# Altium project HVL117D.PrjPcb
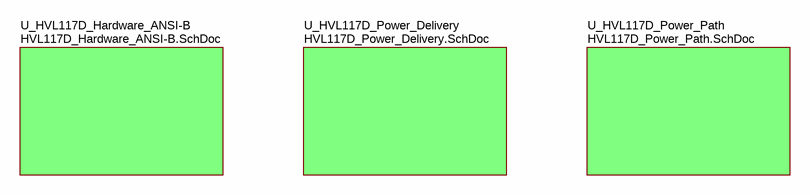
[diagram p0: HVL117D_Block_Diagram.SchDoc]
AssemblyVariant: =VariantName; CopyrightYear: 2015; PCB_Layout: Jacob Ontiveros; PCB_Rev: D; PRJ_Customer: Public Release; PRJ_Engineer: Jacob Ontiveros; PRJ_Number: HVL117; PRJ_Title: TPS65982EVM; SCH_Rev: D; TechSupport: j-ontiveros@ti.com
4 sheets, 220 parts. Net scope: global (net labels, ports and power ports of the same name join across sheets).
Board file: HVL117D.PcbDoc
Sheets:
  HVL117D_Block_Diagram.SchDoc
    U_HVL117D_Hardware_ANSI-B = HVL117D_Hardware_ANSI-B.SchDoc
    U_HVL117D_Power_Delivery = HVL117D_Power_Delivery.SchDoc
    U_HVL117D_Power_Path = HVL117D_Power_Path.SchDoc

## Sheet HVL117D_Block_Diagram.SchDoc: HVL117D_Block_Diagram
size 431 x 279 mm; Date: Not shown in title block; ApprovedBy: Not shown in title block; CheckedBy: Not shown in title block; Author: Not shown in title block; CompanyName: Not shown in title block; Engineer: Not shown in title block; Organization: Not shown in title block; Address1: Not shown in title block; Address2: Not shown in title block; Address3: Not shown in title block; Address4: Not shown in title block; DocumentNumber: 1; Revision: Use project parameter SCH_Rev; SheetNumber: 1; SheetTotal: 4; PageSetup: Record=PageOptions¦CenterHorizontal=True¦CenterVertical=True¦PrintScale=0.64¦XCorrection=1.00¦YCorrection=1.00¦PrintKind=0¦BorderSize=5000000¦LeftOffset=0¦BottomOffset=0¦Orientation=2¦PaperLength=1000¦PaperWidth=1000¦Scale=100¦PaperSource=15¦PrintQuality=600¦MediaType=1¦DitherType=10¦PaperKind=Letter¦PrintScaleMode=1

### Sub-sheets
U_HVL117D_Hardware_ANSI-B = HVL117D_Hardware_ANSI-B.SchDoc: no entries
U_HVL117D_Power_Delivery = HVL117D_Power_Delivery.SchDoc: no entries
U_HVL117D_Power_Path = HVL117D_Power_Path.SchDoc: no entries

## Sheet HVL117D_Hardware_ANSI-B.SchDoc: Hardware
size 431 x 279 mm; Date: Not shown in title block; ApprovedBy: Not shown in title block; CheckedBy: Not shown in title block; Author: Not shown in title block; CompanyName: Not shown in title block; Engineer: Not shown in title block; Organization: Not shown in title block; Address1: Not shown in title block; Address2: Not shown in title block; Address3: Not shown in title block; Address4: Not shown in title block; DocumentNumber: 4; Revision: Use project parameter SCH_Rev; SheetNumber: 4; SheetTotal: 4; PageSetup: Record=PageOptions¦CenterHorizontal=True¦CenterVertical=True¦PrintScale=1.00¦XCorrection=1.00¦YCorrection=1.00¦PrintKind=0¦BorderSize=5000000¦LeftOffset=0¦BottomOffset=0¦Orientation=2¦PaperLength=1000¦PaperWidth=1000¦Scale=100¦PaperSource=15¦PrintQuality=600¦MediaType=1¦DitherType=10¦PaperKind=Letter¦PrintScaleMode=1
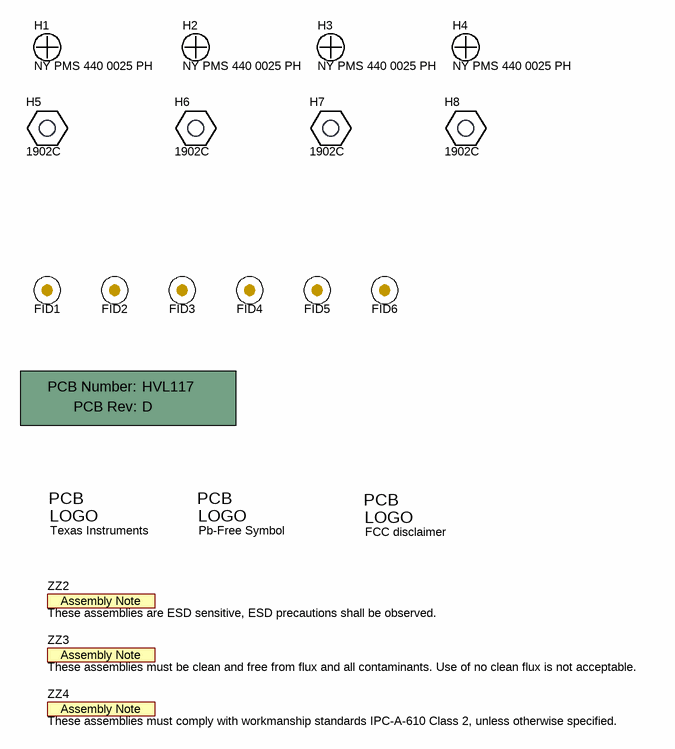
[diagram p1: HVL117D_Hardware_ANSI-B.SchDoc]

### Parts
!PCB1  Printed Circuit Board  (value not drawn)  (mechanical)
FID1  Fiducial  [Fiducial10-20]  (value not drawn)
FID2  Fiducial  [Fiducial10-20]  (value not drawn)
FID3  Fiducial  [Fiducial10-20]  (value not drawn)
FID4  Fiducial  [Fiducial10-20]  (value not drawn)
FID5  Fiducial  [Fiducial10-20]  (value not drawn)
FID6  Fiducial  [Fiducial10-20]  (value not drawn)
H1  NY PMS 440 0025 PH  [NY PMS 440 0025 PH]
H2  NY PMS 440 0025 PH  [NY PMS 440 0025 PH]
H3  NY PMS 440 0025 PH  [NY PMS 440 0025 PH]
H4  NY PMS 440 0025 PH  [NY PMS 440 0025 PH]
H5  1902C  [Keystone_1902C]
H6  1902C  [Keystone_1902C]
H7  1902C  [Keystone_1902C]
H8  1902C  [Keystone_1902C]
Logo1  Texas Instruments  [TI_Stacked_Overlay_Small]  (no BOM)
Logo2  Pb-Free Symbol  [Pb-Free_Overlay_Small]  (no BOM)
Logo3  FCC disclaimer  [FCC_disclaimer_stacked]  (no BOM)
ZZ2  These assemblies are ESD sensitive, ESD precautions shall be observed.  [AssemblyNote]  (no BOM)
ZZ3  These assemblies must be clean and free from flux and all contaminants. Use of no clean flux is not acceptable.  [AssemblyNote]  (no BOM)
ZZ4  These assemblies must comply with workmanship standards IPC-A-610 Class 2, unless otherwise specified.  [AssemblyNote]  (no BOM)

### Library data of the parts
!PCB1 = PCB: Manufacturer: Any; PartNumber: HVL117; SymbolCreator: a0412235
FID1-FID6 = Fiducial: Fiducial mark.  There is nothing to buy or mount.; SymbolCreator: codlsc
H1-H4 = NY PMS 440 0025 PH: Machine Screw, Round, #4-40 x 1/4, Nylon, Philips panhead; Manufacturer: B&F Fastener Supply; CompType: Hardware; SymbolCreator: codlsc; U/M: EA
H5-H8 = 1902C: Standoff, Hex, 0.5"L #4-40 Nylon; Manufacturer: Keystone; CompType: Hardware; SymbolCreator: a0412235
Logo1 = TI_Logo: Texas Instrument Corporate Signature; SymbolCreator: a0412235
Logo2 = Pb-Free: SymbolCreator: a0412235
Logo3 = FCC_disclaimer: SymbolCreator: codlsc
ZZ2-ZZ4 = AssemblyNote: SymbolCreator: codlsc

## Sheet HVL117D_Power_Delivery.SchDoc: TPS65982_TypeC_PD
size 431 x 279 mm; Date: Not shown in title block; ApprovedBy: Not shown in title block; CheckedBy: Not shown in title block; Author: Not shown in title block; CompanyName: Not shown in title block; Engineer: Not shown in title block; Organization: Not shown in title block; Address1: Not shown in title block; Address2: Not shown in title block; Address3: Not shown in title block; Address4: Not shown in title block; DocumentNumber: 2; Revision: Use project parameter SCH_Rev; SheetNumber: 2; SheetTotal: 4; PageSetup: Record=PageOptions|CenterHorizontal=True|CenterVertical=True|PrintScale=0.64|XCorrection=1.00|YCorrection=1.00|PrintKind=0|BorderSize=5000000|LeftOffset=0|BottomOffset=0|Orientation=2|PaperLength=1000|PaperWidth=1000|Scale=100|PaperSource=15|PrintQuality=600|MediaType=1|DitherType=10|PaperKind=Letter|PrintScaleMode=1
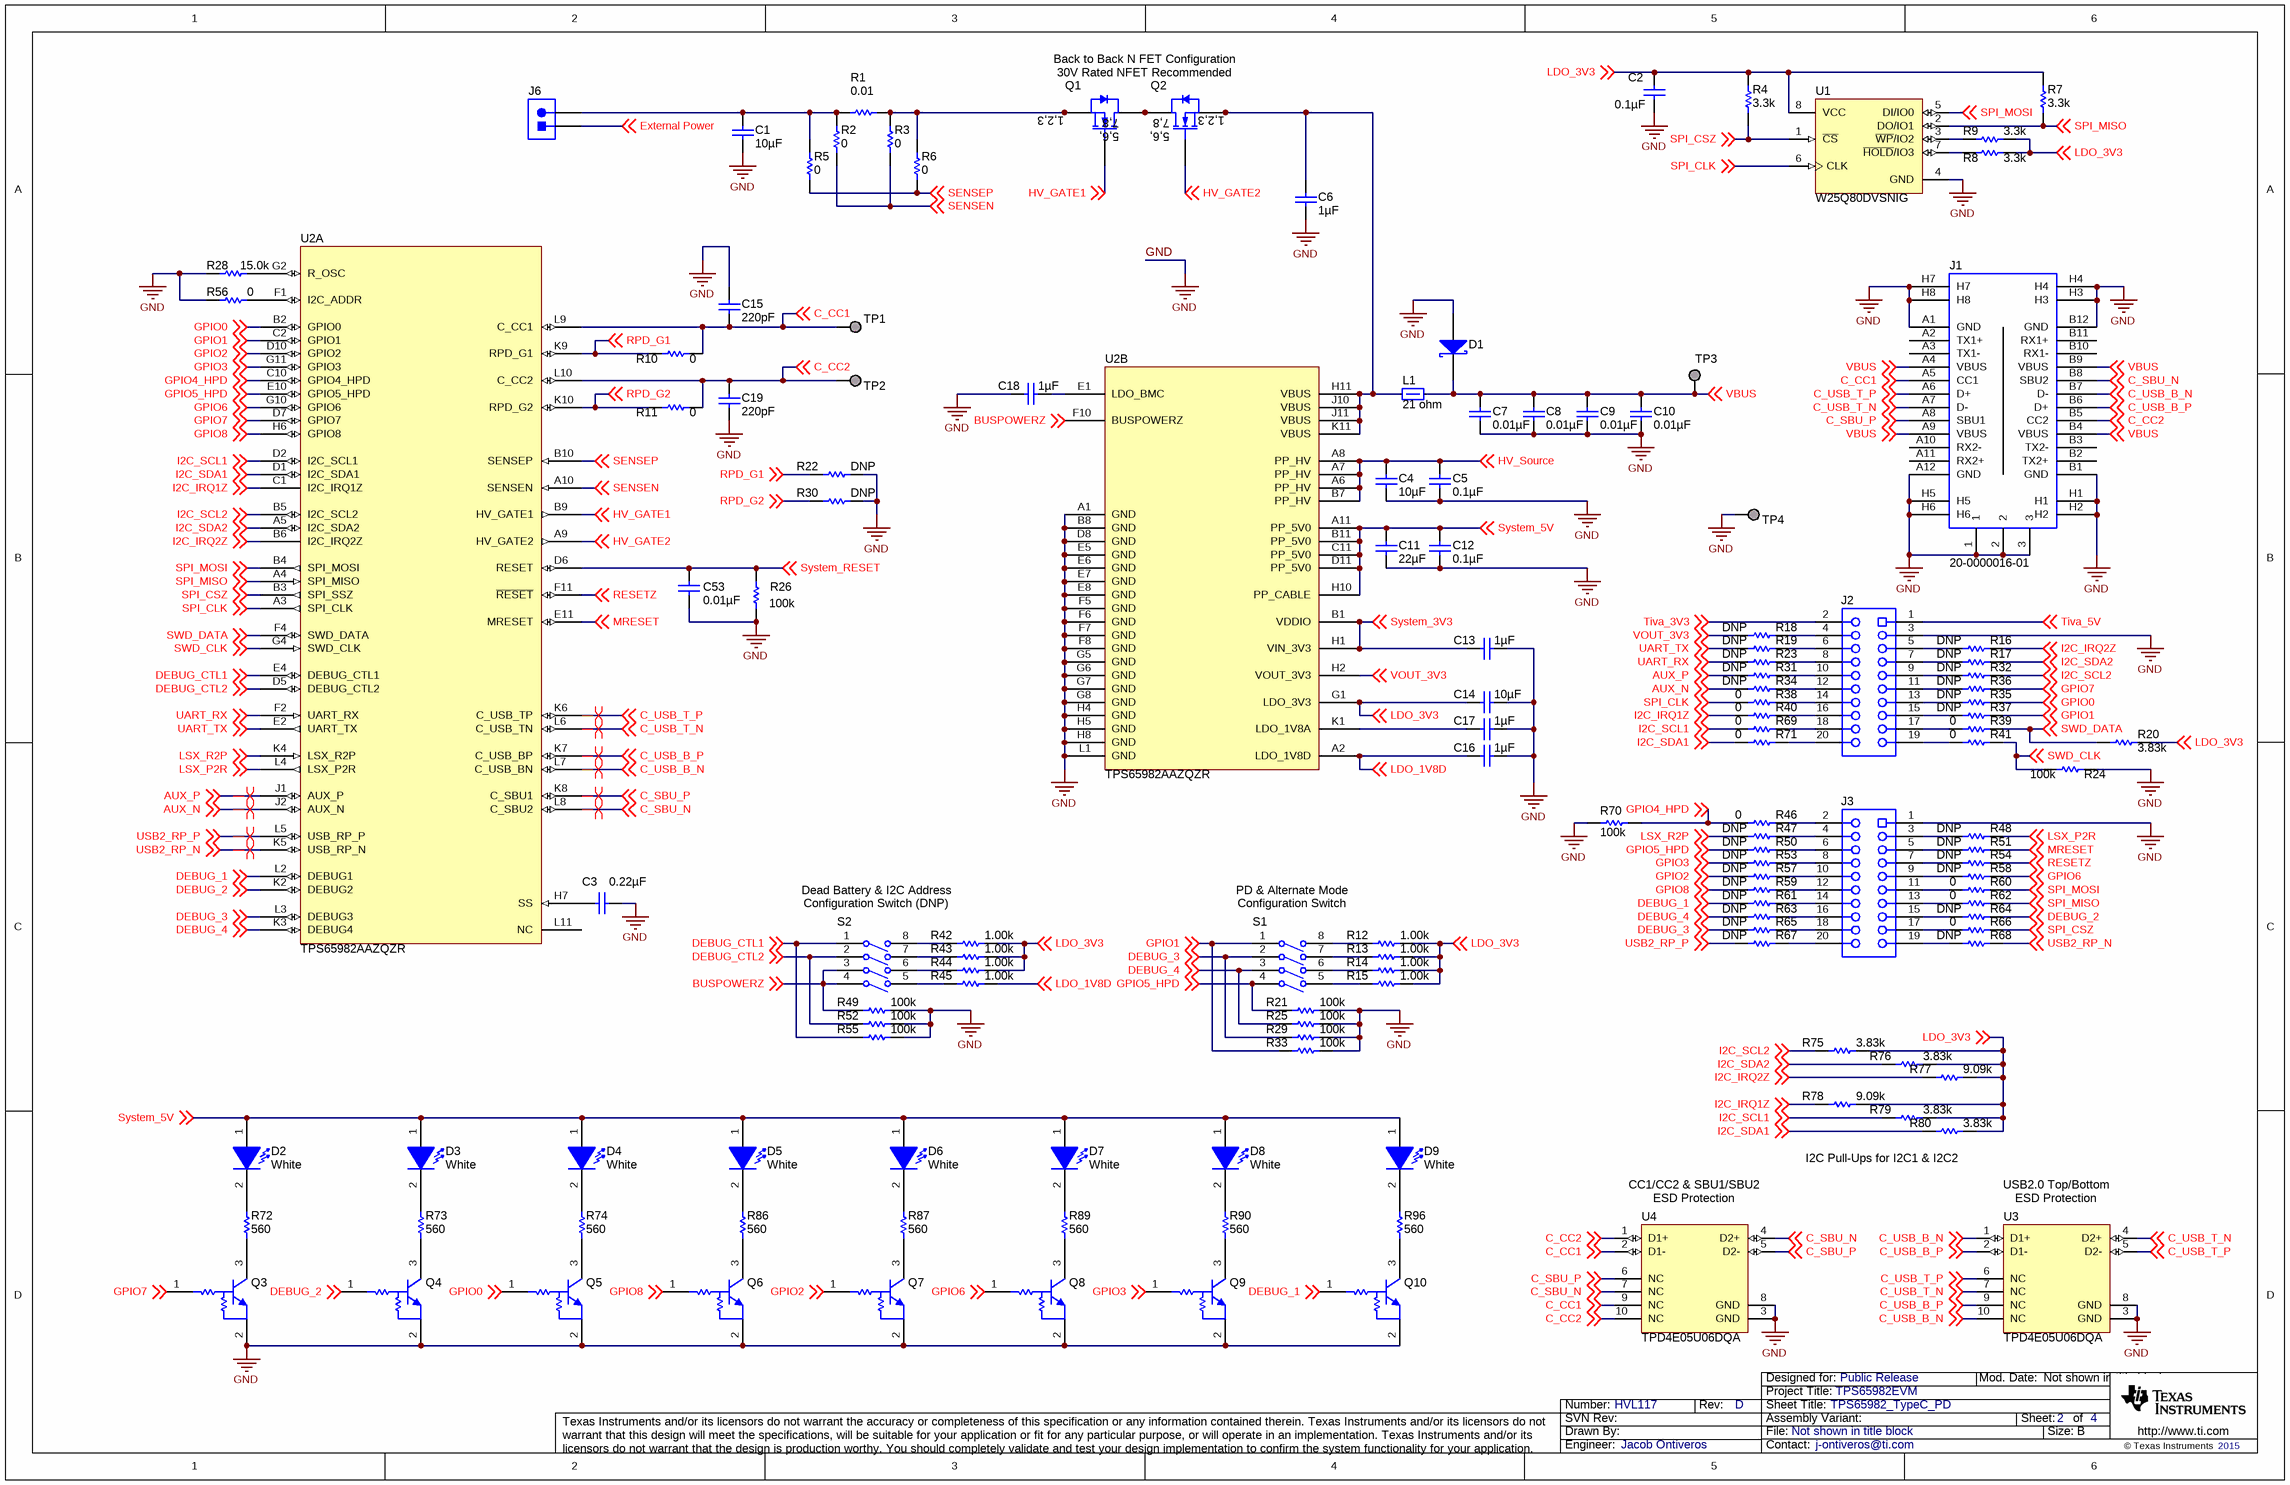
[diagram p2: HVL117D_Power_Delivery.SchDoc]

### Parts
C1  ValueDisplayed: 10µF  [0603]  (hidden comment: GRM188R61E106MA73)
C2  ValueDisplayed: 0.1µF  [0201]  (hidden comment: CL03A104KP3NNNC)
C3  ValueDisplayed: 0.22µF  [0201]  (hidden comment: GRM033R60J224ME90)
C4  ValueDisplayed: 10µF  [0603]  (hidden comment: GRM188R61E106MA73)
C5  ValueDisplayed: 0.1µF  [0402]  (hidden comment: C1005X7R1H104M)
C6  ValueDisplayed: 1µF  [0402]  (hidden comment: C1005JB1V105K050BC)
C7  ValueDisplayed: 0.01µF  [0402]  (hidden comment: GRM155R71H103KA88D)
C8  ValueDisplayed: 0.01µF  [0402]  (hidden comment: GRM155R71H103KA88D)
C9  ValueDisplayed: 0.01µF  [0402]  (hidden comment: GRM155R71H103KA88D)
C10  ValueDisplayed: 0.01µF  [0402]  (hidden comment: GRM155R71H103KA88D)
C11  ValueDisplayed: 22µF  [0603_100]  (hidden comment: GRM188R61A226ME15D)
C12  ValueDisplayed: 0.1µF  [0201]  (hidden comment: CL03A104KP3NNNC)
C13  ValueDisplayed: 1µF  [0201]  (hidden comment: CL03A105MP3NSNC)
C14  ValueDisplayed: 10µF  [0402]  (hidden comment: CL05A106MP5NUNC)
C15  ValueDisplayed: 220pF  [0201]  (hidden comment: GRM033R71E221KA01D)
C16  ValueDisplayed: 1µF  [0201]  (hidden comment: CL03A105MP3NSNC)
C17  ValueDisplayed: 1µF  [0201]  (hidden comment: CL03A105MP3NSNC)
C18  ValueDisplayed: 1µF  [0201]  (hidden comment: CL03A105MP3NSNC)
C19  ValueDisplayed: 220pF  [0201]  (hidden comment: GRM033R71E221KA01D)
C53  ValueDisplayed: 0.01µF  [0201]  (hidden comment: GRM033R61A103KA01D)
D1  B340A-13-F  [SMA]  (value not drawn)
D2  value White  [LW QH8G_White]  (hidden comment: LW QH8G-Q2S2-3K5L-1)
D3  value White  [LW QH8G_White]  (hidden comment: LW QH8G-Q2S2-3K5L-1)
D4  value White  [LW QH8G_White]  (hidden comment: LW QH8G-Q2S2-3K5L-1)
D5  value White  [LW QH8G_White]  (hidden comment: LW QH8G-Q2S2-3K5L-1)
D6  value White  [LW QH8G_White]  (hidden comment: LW QH8G-Q2S2-3K5L-1)
D7  value White  [LW QH8G_White]  (hidden comment: LW QH8G-Q2S2-3K5L-1)
D8  value White  [LW QH8G_White]  (hidden comment: LW QH8G-Q2S2-3K5L-1)
D9  value White  [LW QH8G_White]  (hidden comment: LW QH8G-Q2S2-3K5L-1)
J1  20-0000016-01  [Lintes_20-0000016-01]
J2  PPPC102LFBN-RC  [Sullins_PPPC102LFBN-RC]  (value not drawn)
J3  PPPC102LFBN-RC  [Sullins_PPPC102LFBN-RC]  (value not drawn)
J6  90120-0122  [CONN_90120-0122]  (value not drawn)
L1  value 21 ohm  [0805_HV]  (hidden comment: FBMJ2125HM210NT)
Q1  CSD17309Q3  [TRANS_NexFET_Q3]  (value not drawn)
Q2  CSD17309Q3  [TRANS_NexFET_Q3]  (value not drawn)
Q3  DTC114EUAT106  [SOT-323]  (value not drawn)
Q4  DTC114EUAT106  [SOT-323]  (value not drawn)
Q5  DTC114EUAT106  [SOT-323]  (value not drawn)
Q6  DTC114EUAT106  [SOT-323]  (value not drawn)
Q7  DTC114EUAT106  [SOT-323]  (value not drawn)
Q8  DTC114EUAT106  [SOT-323]  (value not drawn)
Q9  DTC114EUAT106  [SOT-323]  (value not drawn)
Q10  DTC114EUAT106  [SOT-323]  (value not drawn)
R1  value 0.01  [0805_HV]  (hidden comment: WSL0805R0100FEA18)
R2  ValueDisplayed: 0  [0201M]  (hidden comment: ERJ-1GE0R00C)
R3  ValueDisplayed: 0  [0201M]  (hidden comment: ERJ-1GE0R00C)
R4  ValueDisplayed: 3.3k  [0402]  (hidden comment: CRCW04023K30JNED)
R5  ValueDisplayed: 0  [0201M]  (hidden comment: ERJ-1GE0R00C)
R6  ValueDisplayed: 0  [0201M]  (hidden comment: ERJ-1GE0R00C)
R7  ValueDisplayed: 3.3k  [0402]  (hidden comment: CRCW04023K30JNED)
R8  ValueDisplayed: 3.3k  [0402]  (hidden comment: CRCW04023K30JNED)
R9  ValueDisplayed: 3.3k  [0402]  (hidden comment: CRCW04023K30JNED)
R10  ValueDisplayed: 0  [0201M]  (hidden comment: ERJ-1GE0R00C)
R11  ValueDisplayed: 0  [0201M]  (hidden comment: ERJ-1GE0R00C)
R12  ValueDisplayed: 1.00k  [0201M]  (hidden comment: CRCW02011K00FKED)
R13  ValueDisplayed: 1.00k  [0201M]  (hidden comment: CRCW02011K00FKED)
R14  ValueDisplayed: 1.00k  [0201M]  (hidden comment: CRCW02011K00FKED)
R15  ValueDisplayed: 1.00k  [0201M]  (hidden comment: CRCW02011K00FKED)
R16  ValueDisplayed: DNP  [0201M]  (hidden comment: ERJ-1GE0R00C)
R17  ValueDisplayed: DNP  [0201M]  (hidden comment: ERJ-1GE0R00C)
R18  ValueDisplayed: DNP  [0201M]  (hidden comment: ERJ-1GE0R00C)
R19  ValueDisplayed: DNP  [0201M]  (hidden comment: ERJ-1GE0R00C)
R20  ValueDisplayed: 3.83k  [0201M]  (hidden comment: CRCW02013K83FKED)
R21  ValueDisplayed: 100k  [0201M]  (hidden comment: CRCW0201100KFKED)
R22  ValueDisplayed: DNP  [0201M]  (hidden comment: ERJ-1GE0R00C)
R23  ValueDisplayed: DNP  [0201M]  (hidden comment: ERJ-1GE0R00C)
R24  ValueDisplayed: 100k  [0201M]  (hidden comment: CRCW0201100KFKED)
R25  ValueDisplayed: 100k  [0201M]  (hidden comment: CRCW0201100KFKED)
R26  ValueDisplayed: 100k  [0201M]  (hidden comment: CRCW0201100KFKED)
R28  ValueDisplayed: 15.0k  [0402]  (hidden comment: CRCW040215K0FKED)
R29  ValueDisplayed: 100k  [0201M]  (hidden comment: CRCW0201100KFKED)
R30  ValueDisplayed: DNP  [0201M]  (hidden comment: ERJ-1GE0R00C)
R31  ValueDisplayed: DNP  [0201M]  (hidden comment: ERJ-1GE0R00C)
R32  ValueDisplayed: DNP  [0201M]  (hidden comment: ERJ-1GE0R00C)
R33  ValueDisplayed: 100k  [0201M]  (hidden comment: CRCW0201100KFKED)
R34  ValueDisplayed: DNP  [0201M]  (hidden comment: ERJ-1GE0R00C)
R35  ValueDisplayed: DNP  [0201M]  (hidden comment: ERJ-1GE0R00C)
R36  ValueDisplayed: DNP  [0201M]  (hidden comment: ERJ-1GE0R00C)
R37  ValueDisplayed: DNP  [0201M]  (hidden comment: ERJ-1GE0R00C)
R38  ValueDisplayed: 0  [0201M]  (hidden comment: ERJ-1GE0R00C)
R39  ValueDisplayed: 0  [0201M]  (hidden comment: ERJ-1GE0R00C)
R40  ValueDisplayed: 0  [0201M]  (hidden comment: ERJ-1GE0R00C)
R41  ValueDisplayed: 0  [0201M]  (hidden comment: ERJ-1GE0R00C)
R42  ValueDisplayed: 1.00k  [0201M]  (hidden comment: CRCW02011K00FKED)
R43  ValueDisplayed: 1.00k  [0201M]  (hidden comment: CRCW02011K00FKED)
R44  ValueDisplayed: 1.00k  [0201M]  (hidden comment: CRCW02011K00FKED)
R45  ValueDisplayed: 1.00k  [0201M]  (hidden comment: CRCW02011K00FKED)
R46  ValueDisplayed: 0  [0201M]  (hidden comment: ERJ-1GE0R00C)
R47  ValueDisplayed: DNP  [0201M]  (hidden comment: ERJ-1GE0R00C)
R48  ValueDisplayed: DNP  [0201M]  (hidden comment: ERJ-1GE0R00C)
R49  ValueDisplayed: 100k  [0201M]  (hidden comment: CRCW0201100KFKED)
R50  ValueDisplayed: DNP  [0201M]  (hidden comment: ERJ-1GE0R00C)
R51  ValueDisplayed: DNP  [0201M]  (hidden comment: ERJ-1GE0R00C)
R52  ValueDisplayed: 100k  [0201M]  (hidden comment: CRCW0201100KFKED)
R53  ValueDisplayed: DNP  [0201M]  (hidden comment: ERJ-1GE0R00C)
R54  ValueDisplayed: DNP  [0201M]  (hidden comment: ERJ-1GE0R00C)
R55  ValueDisplayed: 100k  [0201M]  (hidden comment: CRCW0201100KFKED)
R56  ValueDisplayed: 0  [0201M]  (hidden comment: ERJ-1GE0R00C)
R57  ValueDisplayed: DNP  [0201M]  (hidden comment: ERJ-1GE0R00C)
R58  ValueDisplayed: DNP  [0201M]  (hidden comment: ERJ-1GE0R00C)
R59  ValueDisplayed: DNP  [0201M]  (hidden comment: ERJ-1GE0R00C)
R60  ValueDisplayed: 0  [0201M]  (hidden comment: ERJ-1GE0R00C)
R61  ValueDisplayed: DNP  [0201M]  (hidden comment: ERJ-1GE0R00C)
R62  ValueDisplayed: 0  [0201M]  (hidden comment: ERJ-1GE0R00C)
R63  ValueDisplayed: DNP  [0201M]  (hidden comment: ERJ-1GE0R00C)
R64  ValueDisplayed: DNP  [0201M]  (hidden comment: ERJ-1GE0R00C)
R65  ValueDisplayed: DNP  [0201M]  (hidden comment: ERJ-1GE0R00C)
R66  ValueDisplayed: 0  [0201M]  (hidden comment: ERJ-1GE0R00C)
R67  ValueDisplayed: DNP  [0201M]  (hidden comment: ERJ-1GE0R00C)
R68  ValueDisplayed: DNP  [0201M]  (hidden comment: ERJ-1GE0R00C)
R69  ValueDisplayed: 0  [0201M]  (hidden comment: ERJ-1GE0R00C)
R70  ValueDisplayed: 100k  [0201M]  (hidden comment: CRCW0201100KFKED)
R71  ValueDisplayed: 0  [0201M]  (hidden comment: ERJ-1GE0R00C)
R72  ValueDisplayed: 560  [0402]  (hidden comment: CRCW0402560RJNED)
R73  ValueDisplayed: 560  [0402]  (hidden comment: CRCW0402560RJNED)
R74  ValueDisplayed: 560  [0402]  (hidden comment: CRCW0402560RJNED)
R75  ValueDisplayed: 3.83k  [0201M]  (hidden comment: CRCW02013K83FKED)
R76  ValueDisplayed: 3.83k  [0201M]  (hidden comment: CRCW02013K83FKED)
R77  ValueDisplayed: 9.09k  [0201M]  (hidden comment: CRCW02019K09FKED)
R78  ValueDisplayed: 9.09k  [0201M]  (hidden comment: CRCW02019K09FKED)
R79  ValueDisplayed: 3.83k  [0201M]  (hidden comment: CRCW02013K83FKED)
R80  ValueDisplayed: 3.83k  [0201M]  (hidden comment: CRCW02013K83FKED)
R86  ValueDisplayed: 560  [0402]  (hidden comment: CRCW0402560RJNED)
R87  ValueDisplayed: 560  [0402]  (hidden comment: CRCW0402560RJNED)
R89  ValueDisplayed: 560  [0402]  (hidden comment: CRCW0402560RJNED)
R90  ValueDisplayed: 560  [0402]  (hidden comment: CRCW0402560RJNED)
R96  ValueDisplayed: 560  [0402]  (hidden comment: CRCW0402560RJNED)
S1  TDA04H0SB1  [SW_TDA04H0SB1]  (value not drawn)
S2  TDA04H0SB1  [SW_TDA04H0SB1]  (value not drawn)
TP1  TESTPOINT  [Keystone_5019]  (value not drawn)
TP2  TESTPOINT  [Keystone_5019]  (value not drawn)
TP3  TESTPOINT  [Keystone_5019]  (value not drawn)
TP4  TESTPOINT  [Keystone_5019]  (value not drawn)
U1  W25Q80DVSNIG  [SOIC-8]
U2  TPS65982AAZQZR  [ZQZ0096A_Oval]  (parts A,B of 2)
U3  TPD4E05U06DQA  [DQA0010A]
U4  TPD4E05U06DQA  [DQA0010A]

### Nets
GND: C1.2 C2.2 C3.2 C4.2 C5.2 C6.2 C7.2 C8.2 C9.2 C10.2 C11.2 C12.2 C13.2 C14.2 C15.2 C16.2 C17.2 C18.2 C19.2 C53.2 D1.2(A) J1.1 J1.2 J1.3 J1.A1(GND) J1.A12(GND) J1.B1(GND) J1.B12(GND) J1.H1 J1.H2 J1.H3 J1.H4 J1.H5 J1.H6 J1.H7 J1.H8 J2.3 J3.1 Q3.2(E) Q4.2(E) Q5.2(E) Q6.2(E) Q7.2(E) Q8.2(E) Q9.2(E) Q10.2(E) R21.2 R22.2 R24.2 R25.2 R26.1 R28.1 R29.2 R30.2 R33.2 R49.2 R52.2 R55.2 R56.1 R70.1 TP4.1 U1.4(GND) U2.A1(GND) U2.B8(GND) U2.D8(GND) U2.E5(GND) U2.E6(GND) U2.E7(GND) U2.E8(GND) U2.F5(GND) U2.F6(GND) U2.F7(GND) U2.F8(GND) U2.G5(GND) U2.G6(GND) U2.G7(GND) U2.G8(GND) U2.H4(GND) U2.H5(GND) U2.H8(GND) U2.L1(GND) U3.3(GND) U3.8(GND) U4.3(GND) U4.8(GND)
AUX_N: R34.2 U2.J2(AUX_N) ; off-sheet AUX_N
AUX_P: R31.2 U2.J1(AUX_P) ; off-sheet AUX_P
BUSPOWERZ: R49.1 S2.3(A3) S2.4(A4) U2.F10(BUSPOWERZ) ; off-sheet BUSPOWERZ
C_CC1: C15.1 J1.A5(CC1) R10.2 TP1.1 U2.L9(C_CC1) U4.2(D1-) U4.9(NC) ; off-sheet C_CC1
C_CC2: C19.1 J1.B5(CC2) R11.2 TP2.1 U2.L10(C_CC2) U4.1(D1+) U4.10(NC) ; off-sheet C_CC2
C_SBU_N: J1.B8(SBU2) U2.L8(C_SBU2) U4.4(D2+) U4.7(NC) ; off-sheet C_SBU_N
C_SBU_P: J1.A8(SBU1) U2.K8(C_SBU1) U4.5(D2-) U4.6(NC) ; off-sheet C_SBU_P
C_USB_B_N: J1.B7(D-) U2.L7(C_USB_BN) U3.1(D1+) U3.10(NC) ; off-sheet C_USB_B_N
C_USB_B_P: J1.B6(D+) U2.K7(C_USB_BP) U3.2(D1-) U3.9(NC) ; off-sheet C_USB_B_P
C_USB_T_N: J1.A7(D-) U2.L6(C_USB_TN) U3.4(D2+) U3.7(NC) ; off-sheet C_USB_T_N
C_USB_T_P: J1.A6(D+) U2.K6(C_USB_TP) U3.5(D2-) U3.6(NC) ; off-sheet C_USB_T_P
DEBUG_1: Q10.1(B) R61.1 U2.L2(DEBUG1) ; off-sheet DEBUG_1
DEBUG_2: Q4.1(B) R64.1 U2.K2(DEBUG2) ; off-sheet DEBUG_2
DEBUG_3: R29.1 R65.1 S1.2(A2) U2.L3(DEBUG3) ; off-sheet DEBUG_3
DEBUG_4: R25.1 R63.1 S1.3(A3) U2.K3(DEBUG4) ; off-sheet DEBUG_4
DEBUG_CTL1: R55.1 S2.1(A1) U2.E4(DEBUG_CTL1) ; off-sheet DEBUG_CTL1
DEBUG_CTL2: R52.1 S2.2(A2) U2.D5(DEBUG_CTL2) ; off-sheet DEBUG_CTL2
External Power: J6.1 ; off-sheet External Power
GPIO0: Q5.1(B) R35.1 U2.B2(GPIO0) ; off-sheet GPIO0
GPIO1: R33.1 R37.1 S1.1(A1) U2.C2(GPIO1) ; off-sheet GPIO1
GPIO2: Q7.1(B) R57.1 U2.D10(GPIO2) ; off-sheet GPIO2
GPIO3: Q9.1(B) R53.1 U2.G11(GPIO3) ; off-sheet GPIO3
GPIO4_HPD: R46.2 R70.2 U2.C10(GPIO4_HPD) ; off-sheet GPIO4_HPD
GPIO5_HPD: R21.1 R50.2 S1.4(A4) U2.E10(GPIO5_HPD) ; off-sheet GPIO5_HPD
GPIO6: Q8.1(B) R58.1 U2.G10(GPIO6) ; off-sheet GPIO6
GPIO7: Q3.1(B) R36.1 U2.D7(GPIO7) ; off-sheet GPIO7
GPIO8: Q6.1(B) R59.1 U2.H6(GPIO8) ; off-sheet GPIO8
HV_GATE1: Q1.4(G) U2.B9(HV_GATE1) ; off-sheet HV_GATE1
HV_GATE2: Q2.4(G) U2.A9(HV_GATE2) ; off-sheet HV_GATE2
HV_Source: C4.1 C5.1 U2.A6(PP_HV) U2.A7(PP_HV) U2.A8(PP_HV) U2.B7(PP_HV) ; off-sheet HV_Source
I2C_IRQ1Z: R40.2 R78.1 U2.C1(I2C_IRQ1Z) ; off-sheet I2C_IRQ1Z
I2C_IRQ2Z: R16.1 R77.1 U2.B6(I2C_IRQ2Z) ; off-sheet I2C_IRQ2Z
I2C_SCL1: R69.2 R79.1 U2.D2(I2C_SCL1) ; off-sheet I2C_SCL1
I2C_SCL2: R32.1 R75.1 U2.B5(I2C_SCL2) ; off-sheet I2C_SCL2
I2C_SDA1: R71.2 R80.1 U2.D1(I2C_SDA1) ; off-sheet I2C_SDA1
I2C_SDA2: R17.1 R76.1 U2.A5(I2C_SDA2) ; off-sheet I2C_SDA2
LDO_1V8D: C16.1 R45.2 U2.A2(LDO_1V8D) ; off-sheet LDO_1V8D
LDO_3V3: C2.1 C14.1 R4.1 R7.1 R8.1 R9.2 R12.2 R13.2 R14.2 R15.2 R20.2 R42.2 R43.2 R44.2 R75.2 R76.2 R77.2 R78.2 R79.2 R80.2 U1.8(VCC) U2.G1(LDO_3V3) ; off-sheet LDO_3V3
LSX_P2R: R48.2 U2.L4(LSX_P2R) ; off-sheet LSX_P2R
LSX_R2P: R47.2 U2.K4(LSX_R2P) ; off-sheet LSX_R2P
MRESET: R51.1 U2.E11(MRESET) ; off-sheet MRESET
RESETZ: R54.1 U2.F11(~{RESET}) ; off-sheet RESETZ
RPD_G1: R10.1 R22.1 U2.K9(RPD_G1) ; off-sheet RPD_G1
RPD_G2: R11.1 R30.1 U2.K10(RPD_G2) ; off-sheet RPD_G2
SENSEN: R2.1 R3.1 U2.A10(SENSEN) ; off-sheet SENSEN
SENSEP: R5.1 R6.1 U2.B10(SENSEP) ; off-sheet SENSEP
SPI_CLK: R38.2 U1.6(CLK) U2.A3(SPI_CLK) ; off-sheet SPI_CLK
SPI_CSZ: R4.2 R66.2 U1.1(~{CS}) U2.B3(SPI_SSZ) ; off-sheet SPI_CSZ
SPI_MISO: R7.2 R62.1 U1.2(DO/IO1) U2.A4(SPI_MISO) ; off-sheet SPI_MISO
SPI_MOSI: R60.1 U1.5(DI/IO0) U2.B4(SPI_MOSI) ; off-sheet SPI_MOSI
SWD_CLK: R24.1 R41.1 U2.G4(SWD_CLK) ; off-sheet SWD_CLK
SWD_DATA: R20.1 R39.1 U2.F4(SWD_DATA) ; off-sheet SWD_DATA
System_3V3: C13.1 U2.B1(VDDIO) U2.H1(VIN_3V3) ; off-sheet System_3V3
System_5V: C11.1 C12.1 D2.1(A) D3.1(A) D4.1(A) D5.1(A) D6.1(A) D7.1(A) D8.1(A) D9.1(A) U2.A11(PP_5V0) U2.B11(PP_5V0) U2.C11(PP_5V0) U2.D11(PP_5V0) U2.H10(PP_CABLE) ; off-sheet System_5V
System_RESET: C53.1 R26.2 U2.D6(RESET) ; off-sheet System_RESET
Tiva_3V3: J2.2 ; off-sheet Tiva_3V3
Tiva_5V: J2.1 ; off-sheet Tiva_5V
UART_RX: R23.2 U2.F2(UART_RX) ; off-sheet UART_RX
UART_TX: R19.1 U2.E2(UART_TX) ; off-sheet UART_TX
USB2_RP_N: R68.2 U2.K5(USB_RP_N) ; off-sheet USB2_RP_N
USB2_RP_P: R67.2 U2.L5(USB_RP_P) ; off-sheet USB2_RP_P
VBUS: C7.1 C8.1 C9.1 C10.1 D1.1(K) J1.A4(VBUS) J1.A9(VBUS) J1.B4(VBUS) J1.B9(VBUS) L1.2 TP3.1 ; off-sheet VBUS
VOUT_3V3: R18.1 U2.H2(VOUT_3V3) ; off-sheet VOUT_3V3
NetC1_1: C1.1 J6.2 R1.1 R2.2 R5.2
NetC3_1: C3.1 U2.H7(SS)
NetC6_1: C6.1 L1.1 Q2.1(S) Q2.2(S) Q2.3(S) U2.H11(VBUS) U2.J10(VBUS) U2.J11(VBUS) U2.K11(VBUS)
NetC17_1: C17.1 U2.K1(LDO_1V8A)
NetC18_1: C18.1 U2.E1(LDO_BMC)
NetD2_2: D2.2(K) R72.2
NetD3_2: D3.2(K) R73.2
NetD4_2: D4.2(K) R74.2
NetD5_2: D5.2(K) R86.2
NetD6_2: D6.2(K) R87.2
NetD7_2: D7.2(K) R89.2
NetD8_2: D8.2(K) R90.2
NetD9_2: D9.2(K) R96.2
NetJ2_4: J2.4 R18.2
NetJ2_5: J2.5 R16.2
NetJ2_6: J2.6 R19.2
NetJ2_7: J2.7 R17.2
NetJ2_8: J2.8 R23.1
NetJ2_9: J2.9 R32.2
NetJ2_10: J2.10 R31.1
NetJ2_11: J2.11 R36.2
NetJ2_12: J2.12 R34.1
NetJ2_13: J2.13 R35.2
NetJ2_14: J2.14 R38.1
NetJ2_15: J2.15 R37.2
NetJ2_16: J2.16 R40.1
NetJ2_17: J2.17 R39.2
NetJ2_18: J2.18 R69.1
NetJ2_19: J2.19 R41.2
NetJ2_20: J2.20 R71.1
NetJ3_2: J3.2 R46.1
NetJ3_3: J3.3 R48.1
NetJ3_4: J3.4 R47.1
NetJ3_5: J3.5 R51.2
NetJ3_6: J3.6 R50.1
NetJ3_7: J3.7 R54.2
NetJ3_8: J3.8 R53.2
NetJ3_9: J3.9 R58.2
NetJ3_10: J3.10 R57.2
NetJ3_11: J3.11 R60.2
NetJ3_12: J3.12 R59.2
NetJ3_13: J3.13 R62.2
NetJ3_14: J3.14 R61.2
NetJ3_15: J3.15 R64.2
NetJ3_16: J3.16 R63.2
NetJ3_17: J3.17 R66.1
NetJ3_18: J3.18 R65.2
NetJ3_19: J3.19 R68.1
NetJ3_20: J3.20 R67.1
NetQ1_1: Q1.1(S) Q1.2(S) Q1.3(S) R1.2 R3.2 R6.2
NetQ1_5: Q1.5(D) Q1.6(D) Q1.7(D) Q1.8(D) Q2.5(D) Q2.6(D) Q2.7(D) Q2.8(D)
NetQ3_3: Q3.3(C) R72.1
NetQ4_3: Q4.3(C) R73.1
NetQ5_3: Q5.3(C) R74.1
NetQ6_3: Q6.3(C) R86.1
NetQ7_3: Q7.3(C) R87.1
NetQ8_3: Q8.3(C) R89.1
NetQ9_3: Q9.3(C) R90.1
NetQ10_3: Q10.3(C) R96.1
NetR8_2: R8.2 U1.7(~{HOLD}/IO3)
NetR9_1: R9.1 U1.3(~{WP}/IO2)
NetR12_1: R12.1 S1.8(B1)
NetR13_1: R13.1 S1.7(B2)
NetR14_1: R14.1 S1.6(B3)
NetR15_1: R15.1 S1.5(B4)
NetR28_2: R28.2 U2.G2(R_OSC)
NetR42_1: R42.1 S2.8(B1)
NetR43_1: R43.1 S2.7(B2)
NetR44_1: R44.1 S2.6(B3)
NetR45_1: R45.1 S2.5(B4)
NetR56_2: R56.2 U2.F1(I2C_ADDR)

Not connected (* = marked no-connect by the designer): J1 A2(TX1+) A3(TX1-) A10(RX2-) A11(RX2+) B2(TX2+) B3(TX2-) B10(RX1-) B11(RX1+); U2 L11(NC)

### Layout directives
differential pair: AUX_N, AUX_P, C_SBU_N, C_SBU_P, C_USB_B_N, C_USB_B_P, C_USB_T_N, C_USB_T_P, USB2_RP_N, USB2_RP_P

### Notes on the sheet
- Back to Back N FET Configuration
- 30V Rated NFET Recommended
- Dead Battery & I2C Address
- Configuration Switch (DNP)
- PD & Alternate Mode
- Configuration Switch
- I2C Pull-Ups for I2C1 & I2C2
- (near U4) CC1/CC2 & SBU1/SBU2
- (near U4) ESD Protection
- USB2.0 Top/Bottom
- (near U3) ESD Protection

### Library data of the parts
C1 C4 = GRM188R61E106MA73: CAP, CERM, 10 µF, 25 V, +/- 20%, X5R, 0603; Manufacturer: MuRata; Polarized: N; CompType: Capacitor; Value: 10uF; U/M: EA; Cap_F: 0.00001; Tolerance_%: 20; Value1: Unknown; VDC_V: 25; Value2: 25V; TaMin_C: -55; TaMax_C: 85
C2 C12 = CL03A104KP3NNNC: CAP, CERM, 0.1 µF, 10 V, +/- 10%, X5R, 0201; Manufacturer: Samsung; Polarized: N; CompType: Capacitor; Value: 0.1uF; U/M: EA; Cap_F: 0.0000001; Tolerance_%: 10; Value1: Unknown; Value2: 10V; TaMin_C: -55; TaMax_C: 85
C3 = GRM033R60J224ME90: CAP, CERM, 0.22 µF, 6.3 V, +/- 20%, X5R, 0201; Manufacturer: MuRata; Polarized: N; CompType: Capacitor; Value: 0.22uF; U/M: EA; Cap_F: 0.00000022; Tolerance_%: 20; Value1: Unknown; VDC_V: 6.3; Value2: 6.3V; TaMin_C: -55; TaMax_C: 85
C5 = C1005X7R1H104M: CAP, CERM, 0.1 µF, 50 V, +/- 20%, C0G/NP0, 0402; Manufacturer: TDK; Polarized: N; CompType: Capacitor; Value: 0.1uF; U/M: EA; Cap_F: 0.0000001; Tolerance_%: 20; Value1: Unknown; VDC_V: 50; Value2: 50V; TaMin_C: -55; TaMax_C: 125
C6 = C1005JB1V105K050BC: CAP, CERM, 1 µF, 35 V, +/- 10%, JB, 0402; Manufacturer: TDK; Polarized: N; CompType: Capacitor; Value: 1uF; U/M: EA; Cap_F: 0.000001; Tolerance_%: 10; Value1: Unknown; VDC_V: 35; Value2: 35V; TaMin_C: -25; TaMax_C: 85
C7-C10 = GRM155R71H103KA88D: CAP, CERM, 0.01 µF, 50 V, +/- 10%, X7R, 0402; Manufacturer: MuRata; Polarized: N; CompType: Capacitor; Value: 0.01uF; U/M: EA; Cap_F: 0.00000001; Tolerance_%: 10; Value1: Unknown; VDC_V: 50; Value2: 50V; TaMin_C: -55; TaMax_C: 125
C11 = GRM188R61A226ME15D: CAP, CERM, 22 µF, 10 V, +/- 20%, X5R, 0603; Manufacturer: MuRata; Polarized: N; CompType: Capacitor; Value: 22uF; U/M: EA; Cap_F: 0.000022; Tolerance_%: 20; Value1: Unknown; VDC_V: 10; Value2: 10V; TaMin_C: -55; TaMax_C: 85; Cap_Case: 0603
C13 C16-C18 = CL03A105MP3NSNC: CAP, CERM, 1 µF, 10 V, +/- 20%, X5R, 0201; Manufacturer: Samsung; Polarized: N; CompType: Capacitor; Value: 1uF; U/M: EA; Cap_F: 0.000001; Tolerance_%: 20; Value1: Unknown; VDC_V: 10; Value2: 10V; TaMin_C: -55; TaMax_C: 85
C14 = CL05A106MP5NUNC: CAP, CERM, 10 µF, 10 V, +/- 20%, X5R, 0402; Manufacturer: Samsung; Polarized: N; CompType: Capacitor; Value: 10uF; U/M: EA; Cap_F: 0.00001; Tolerance_%: 20; Value1: Unknown; VDC_V: 10; Value2: 10V; TaMin_C: -55; TaMax_C: 85
C15 C19 = GRM033R71E221KA01D: CAP, CERM, 220 pF, 25 V, +/- 10%, X7R, 0201; Manufacturer: MuRata; Polarized: N; CompType: Capacitor; Value: 220pF; U/M: EA; Cap_F: 0.00000000022; Tolerance_%: 10; Value1: Unknown; VDC_V: 25; Value2: 25V; TaMin_C: -55; TaMax_C: 125
C53 = GRM033R61A103KA01D: CAP, CERM, 0.01 µF, 10 V, +/- 10%, X5R, 0201; Manufacturer: MuRata; Polarized: N; CompType: Capacitor; Value: 0.01uF; U/M: EA; Cap_F: 0.00000001; Tolerance_%: 10; Value1: Unknown; Value2: 10V; TaMin_C: -55; TaMax_C: 85
D1 = B340A-13-F: Diode, Schottky, 40 V, 3 A, SMA; Manufacturer: Diodes Inc.; U/M: EA; Vf_V: 0.5; Value: 40V; Value1: 3A; Value2: 0.5V; Io_A: 3; Vr_V: 40; TJmax_C: 125; RJC_CperW: 25
D2-D9 = LW QH8G-Q2S2-3K5L-1: LED, White, SMD; Manufacturer: OSRAM; Vf_V: 2.8; Value2: 2.8V; Io_A: 0.005; Vr_V: 5; Ir_A: 1e-008; Tjmax_C: 95; Value1: W; Angle: 120; U/M: EA
J1 = 20-0000016-01: Connector, Receptacle, USB Type C, R/A, SMT; Manufacturer: Lintes Technology; SymbolCreator: Altium; U/M: EA
J2 J3 = PPPC102LFBN-RC: Receptacle, 100mil, 10x2, Gold, TH; Manufacturer: Sullins Connector Solutions; SymbolCreator: a0412235; U/M: EA
J6 = 90120-0122: Header, 100mil, 2x1, Tin, TH; Manufacturer: Molex; SymbolCreator: a0412235; U/M: EA
L1 = FBMJ2125HM210NT: Ferrite Bead, 21 ohm @ 100MHz, 6A, 0805; Manufacturer: Taiyo Yuden; Imax_A: 6; DCR_ohm: 0.004; Value1: 0.004 ohm; ZTyp@100MHz_Ohm: 21
Q1 Q2 = CSD17309Q3: MOSFET, N-CH, 30 V, 60 A, SON 3.3x3.3mm; Manufacturer: Texas Instruments; Alternate Manufacturer: None; U/M: EA; ChType: N; Value: 30V; VdsMax_V: 30; Value1: 0.0049 ohm; Rdson45_ohm: 0.0049; Value2: 7.5 nC; QgTyp_nC: 7.5; Vgs_V: 10; IdsMax_A: 60
Q3-Q10 = DTC114EUAT106, Rohm: Transistor, NPN, 50 V, 0.05 A, SOT-323; Manufacturer: Rohm; SymbolCreator: a0411947; PNP: 0; NPN: 1; Vceo_V: 50; Vcesat1_V: 0.3; Value: 50 V; IcRated_A: 0.05; Value1: 0.05 A; TaMin_C: -55; TaMax_C: 150; CompType: BJT; U/M: EA
R1 = WSL0805R0100FEA18: RES, 0.01 ohm, 1%, 0.25W, 0805; Manufacturer: Vishay-Dale; CompType: Resistor; Value_Code: R010; Tolerance_%: 1; Power_W: 0.25; TempCo: 75 ppm/C; EIA_Code: E96; U/M: EA
R2 R3 R5 R6 R10 R11 R16-R19 R22 R23 R30-R32 R34-R41 R46-R48 R50 R51 R53 R54 R56-R69 R71 = ERJ-1GE0R00C: RES, 0, 5%, 0.05 W, 0201; Manufacturer: Panasonic; CompType: Resistor; Value: 0; Value_Code: 0000; Tolerance_%: 5; Power_W: 0.05; Value2: 0.05W; VDC_V: 15; TempCo: 600 ppm/C; EIA_Code: E24; U/M: EA
R4 R7-R9 = CRCW04023K30JNED: RES, 3.3 k, 5%, 0.063 W, 0402; Manufacturer: Vishay-Dale; CompType: Resistor; Value: 3.3k; Res_ohm: 3300; Value_Code: 3k30; Tolerance_%: 5; Power_W: 0.063; Value2: 0.063W; VDC_V: 50; TempCo: 200 ppm/C; EIA_Code: E24; U/M: EA
R12-R15 R42-R45 = CRCW02011K00FKED: RES, 1.00 k, 1%, 0.05 W, 0201; Manufacturer: Vishay-Dale; CompType: Resistor; Value: 1.00k; Res_ohm: 1000; Value_Code: 1k00; Tolerance_%: 1; Power_W: 0.05; Value2: 0.05W; VDC_V: 30; TempCo: 100 ppm/C; EIA_Code: E96; U/M: EA
R20 R75 R76 R79 R80 = CRCW02013K83FKED: RES, 3.83 k, 1%, 0.05 W, 0201; Manufacturer: Vishay-Dale; CompType: Resistor; Value: 3.83k; Res_ohm: 3830; Value_Code: 3k83; Tolerance_%: 1; Power_W: 0.05; Value2: 0.05W; VDC_V: 30; TempCo: 100 ppm/C; EIA_Code: E96; U/M: EA
R21 R24-R26 R29 R33 R49 R52 R55 R70 = CRCW0201100KFKED: RES, 100 k, 1%, 0.05 W, 0201; Manufacturer: Vishay-Dale; CompType: Resistor; Value: 100k; Res_ohm: 100000; Tolerance_%: 1; Power_W: 0.05; Value2: 0.05W; VDC_V: 30; TempCo: 100 ppm/C; EIA_Code: E96; U/M: EA
R28 = CRCW040215K0FKED: RES, 15.0 k, 1%, 0.063 W, 0402; Manufacturer: Vishay-Dale; CompType: Resistor; Value: 15.0k; Res_ohm: 15000; Value_Code: 15k0; Tolerance_%: 1; Power_W: 0.063; Value2: 0.063W; VDC_V: 50; TempCo: 100 ppm/C; EIA_Code: E96; U/M: EA
R72-R74 R86 R87 R89 R90 R96 = CRCW0402560RJNED: RES, 560, 5%, 0.063 W, 0402; Manufacturer: Vishay-Dale; CompType: Resistor; Value: 560; Value_Code: 560R; Tolerance_%: 5; Power_W: 0.063; Value2: 0.063W; VDC_V: 50; TempCo: 200 ppm/C; EIA_Code: E24; U/M: EA
R77 R78 = CRCW02019K09FKED: RES, 9.09 k, 1%, 0.05 W, 0201; Manufacturer: Vishay-Dale; CompType: Resistor; Value: 9.09k; Res_ohm: 9090; Value_Code: 9k09; Tolerance_%: 1; Power_W: 0.05; Value2: 0.05W; VDC_V: 30; TempCo: 100 ppm/C; EIA_Code: E96; U/M: EA
S1 S2 = TDA04H0SB1: DIP Switch, SPST 4Pos, Slide, SMT; Manufacturer: C&K Components; SymbolCreator: a0412235; VDC_V: 24; SwitchFunction: Off-On; PositionCount: 4; CurrentRating_mA: 20
TP1-TP4 = 5019: Test Point, Miniature, SMT; Manufacturer: Keystone; CompType: Test Point Loop; U/M: EA
U1 = W25Q80DVSNIG: 3V, 8Mbit, Serial Flash Memory with Dual and Qual SPI, SOIC-8; Manufacturer: Winbond; SymbolCreator: Altium
U2 = TPS65982AAZQZR: TPS65982 Preview Specification, ZQZ0096A; Manufacturer: Texas Instruments; SymbolCreator: Altium; CompType: IC; U/M: EA
U3 U4 = TPD4E05U06DQA: 1, 4, 6 CHANNEL PROTECTION SOLUTION FOR SUPER-SPEED (UP TO 6 GBPS) INTERFACE, DQA0010A; Alternate Manufacturer: None; Manufacturer: Texas Instruments; SymbolCreator: a0411947; CompType: IC; U/M: EA

## Sheet HVL117D_Power_Path.SchDoc: Power Path Supplies
size 431 x 279 mm; Date: Not shown in title block; ApprovedBy: Not shown in title block; CheckedBy: Not shown in title block; Author: Not shown in title block; CompanyName: Not shown in title block; Engineer: Not shown in title block; Organization: Not shown in title block; Address1: Not shown in title block; Address2: Not shown in title block; Address3: Not shown in title block; Address4: Not shown in title block; DocumentNumber: 3; Revision: Use project parameter SCH_Rev; SheetNumber: 3; SheetTotal: 4; PageSetup: Record=PageOptions|CenterHorizontal=True|CenterVertical=True|PrintScale=0.64|XCorrection=1.00|YCorrection=1.00|PrintKind=0|BorderSize=5000000|LeftOffset=0|BottomOffset=0|Orientation=2|PaperLength=1000|PaperWidth=1000|Scale=100|PaperSource=15|PrintQuality=600|MediaType=1|DitherType=10|PaperKind=Letter|PrintScaleMode=1
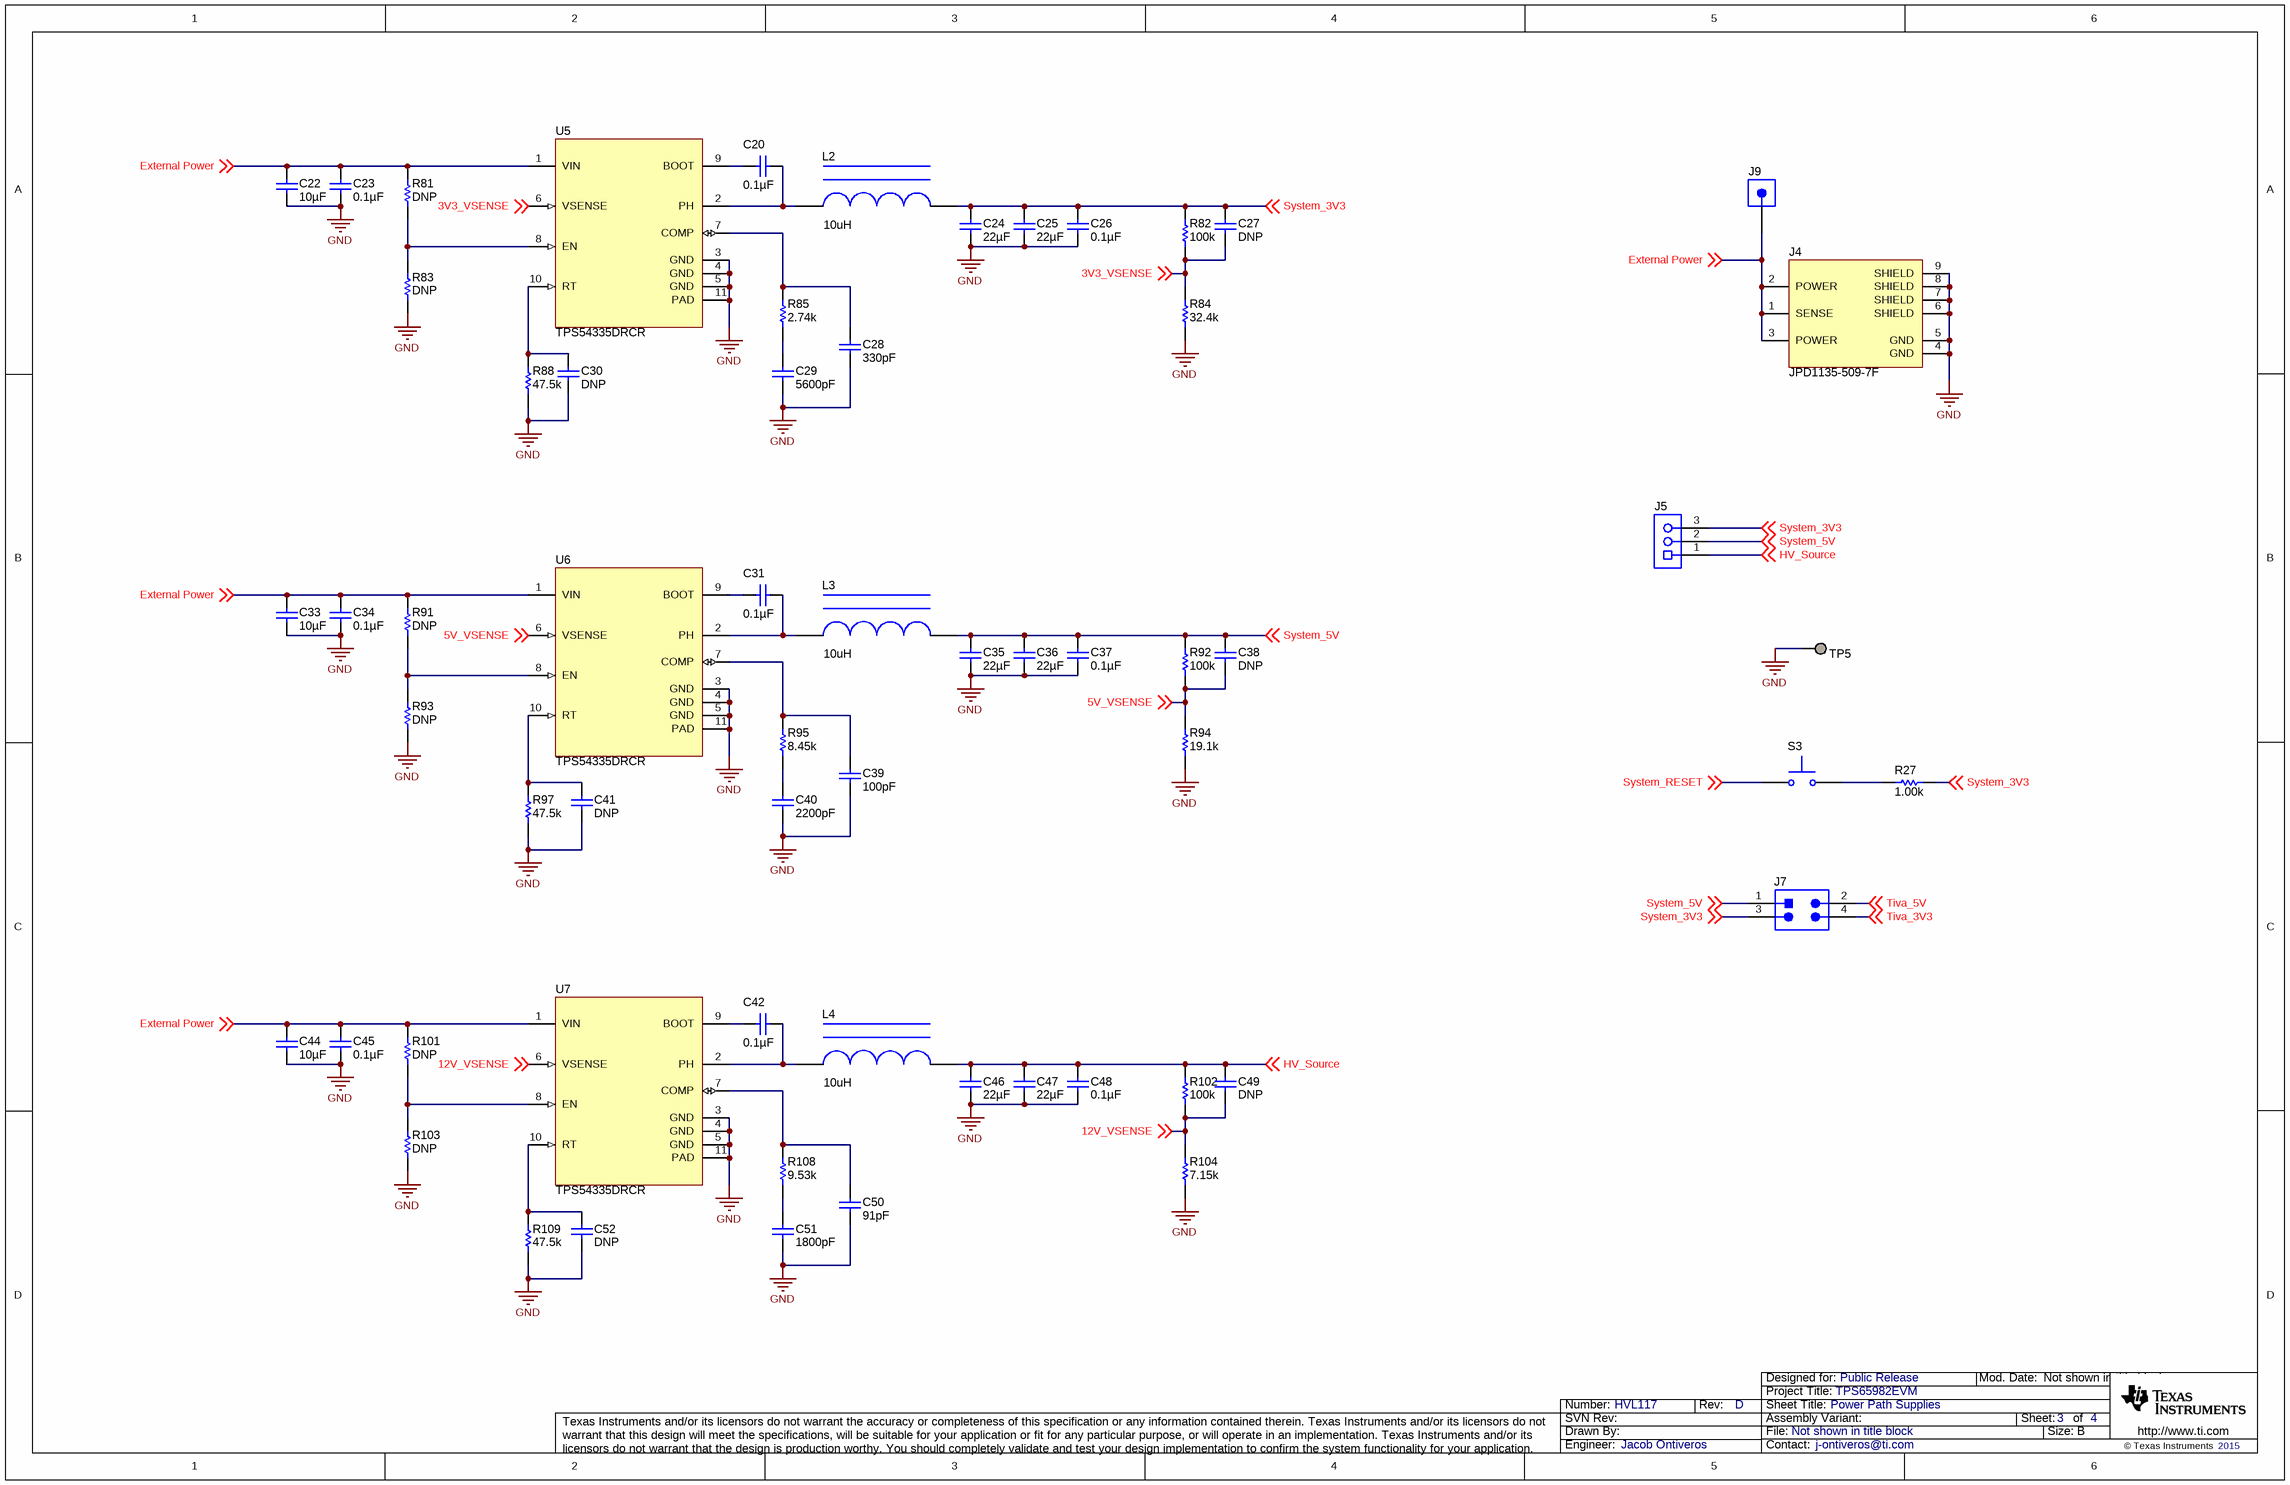
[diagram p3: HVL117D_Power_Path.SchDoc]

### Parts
C20  ValueDisplayed: 0.1µF  [0402]  (hidden comment: C1005X7R1H104M)
C22  ValueDisplayed: 10µF  [0805_HV]  (hidden comment: C2012X5R1E106K125AB)
C23  ValueDisplayed: 0.1µF  [0402]  (hidden comment: C1005X7R1H104M)
C24  ValueDisplayed: 22µF  [0805_HV]  (hidden comment: C2012X5R1V226M125AC)
C25  ValueDisplayed: 22µF  [0805_HV]  (hidden comment: C2012X5R1V226M125AC)
C26  ValueDisplayed: 0.1µF  [0402]  (hidden comment: C1005X7R1H104M)
C27  ValueDisplayed: DNP  [0402]  (hidden comment: GRM1555C1H121JA01D)
C28  ValueDisplayed: 330pF  [0402]  (hidden comment: C1005C0G1H331J)
C29  ValueDisplayed: 5600pF  [0402]  (hidden comment: GRM155R71H562KA88D)
C30  ValueDisplayed: DNP  [0402]  (hidden comment: GRM1555C1H121JA01D)
C31  ValueDisplayed: 0.1µF  [0402]  (hidden comment: C1005X7R1H104M)
C33  ValueDisplayed: 10µF  [0805_HV]  (hidden comment: C2012X5R1E106K125AB)
C34  ValueDisplayed: 0.1µF  [0402]  (hidden comment: C1005X7R1H104M)
C35  ValueDisplayed: 22µF  [0805_HV]  (hidden comment: C2012X5R1V226M125AC)
C36  ValueDisplayed: 22µF  [0805_HV]  (hidden comment: C2012X5R1V226M125AC)
C37  ValueDisplayed: 0.1µF  [0402]  (hidden comment: C1005X7R1H104M)
C38  ValueDisplayed: DNP  [0402]  (hidden comment: GRM1555C1H121JA01D)
C39  ValueDisplayed: 100pF  [0402]  (hidden comment: CC0402KRX7R9BB101)
C40  ValueDisplayed: 2200pF  [0402]  (hidden comment: GRM155R61H222KA01D)
C41  ValueDisplayed: DNP  [0402]  (hidden comment: GRM1555C1H121JA01D)
C42  ValueDisplayed: 0.1µF  [0402]  (hidden comment: C1005X7R1H104M)
C44  ValueDisplayed: 10µF  [0805_HV]  (hidden comment: C2012X5R1E106K125AB)
C45  ValueDisplayed: 0.1µF  [0402]  (hidden comment: C1005X7R1H104M)
C46  ValueDisplayed: 22µF  [0805_HV]  (hidden comment: C2012X5R1V226M125AC)
C47  ValueDisplayed: 22µF  [0805_HV]  (hidden comment: C2012X5R1V226M125AC)
C48  ValueDisplayed: 0.1µF  [0402]  (hidden comment: C1005X7R1H104M)
C49  ValueDisplayed: DNP  [0402]  (hidden comment: GRM1555C1H121JA01D)
C50  ValueDisplayed: 91pF  [0402]  (hidden comment: GRM1555C1H910JA01D)
C51  ValueDisplayed: 1800pF  [0402]  (hidden comment: GRM155R71H182KA01D)
C52  ValueDisplayed: DNP  [0402]  (hidden comment: GRM1555C1H121JA01D)
J4  JPD1135-509-7F  [CONN_JPD1135-509]
J5  PPPC031LFBN-RC  [Sullins_PPPC031LFBN-RC]  (value not drawn)
J7  15-91-2040  [Molex_15-91-2040]  (value not drawn)
J9  1040  [CONN_1040]  (value not drawn)  (graphical)
L2  value 10uH  [ASPI-0630LR]  (hidden comment: ASPI-0630LR-100M-T15)
L3  value 10uH  [ASPI-0630LR]  (hidden comment: ASPI-0630LR-100M-T15)
L4  value 10uH  [ASPI-0630LR]  (hidden comment: ASPI-0630LR-100M-T15)
R27  ValueDisplayed: 1.00k  [0201M]  (hidden comment: CRCW02011K00FKED)
R81  ValueDisplayed: DNP  [0402]  (hidden comment: CRCW0402220KJNED)
R82  ValueDisplayed: 100k  [0402]  (hidden comment: CRCW0402100KFKED)
R83  ValueDisplayed: DNP  [0402]  (hidden comment: CRCW040243K2FKED)
R84  ValueDisplayed: 32.4k  [0402]  (hidden comment: CRCW040232K4FKED)
R85  ValueDisplayed: 2.74k  [0402]  (hidden comment: CRCW04022K74FKED)
R88  ValueDisplayed: 47.5k  [0402]  (hidden comment: CRCW040247K5FKED)
R91  ValueDisplayed: DNP  [0402]  (hidden comment: CRCW0402220KJNED)
R92  ValueDisplayed: 100k  [0402]  (hidden comment: CRCW0402100KFKED)
R93  ValueDisplayed: DNP  [0402]  (hidden comment: CRCW040243K2FKED)
R94  ValueDisplayed: 19.1k  [0402]  (hidden comment: CRCW040219K1FKED)
R95  ValueDisplayed: 8.45k  [0402]  (hidden comment: CRCW04028K45FKED)
R97  ValueDisplayed: 47.5k  [0402]  (hidden comment: CRCW040247K5FKED)
R101  ValueDisplayed: DNP  [0402]  (hidden comment: CRCW0402220KJNED)
R102  ValueDisplayed: 100k  [0402]  (hidden comment: CRCW0402100KFKED)
R103  ValueDisplayed: DNP  [0402]  (hidden comment: CRCW040243K2FKED)
R104  ValueDisplayed: 7.15k  [0402]  (hidden comment: CRCW04027K15FKED)
R108  ValueDisplayed: 9.53k  [0402]  (hidden comment: CRCW04029K53FKED)
R109  ValueDisplayed: 47.5k  [0402]  (hidden comment: CRCW040247K5FKED)
S3  B3U-1000P  [SW_B3U-1000P]  (value not drawn)
TP5  TESTPOINT  [Keystone_5019]  (value not drawn)
U5  TPS54335DRCR  [DRC0010J]
U6  TPS54335DRCR  [DRC0010J]
U7  TPS54335DRCR  [DRC0010J]

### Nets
GND: C22.2 C23.2 C24.2 C25.2 C26.2 C28.2 C29.2 C30.2 C33.2 C34.2 C35.2 C36.2 C37.2 C39.2 C40.2 C41.2 C44.2 C45.2 C46.2 C47.2 C48.2 C50.2 C51.2 C52.2 J4.4(GND) J4.5(GND) J4.6(SHIELD) J4.7(SHIELD) J4.8(SHIELD) J4.9(SHIELD) R83.1 R84.1 R88.1 R93.1 R94.1 R97.1 R103.1 R104.1 R109.1 TP5.1 U5.3(GND) U5.4(GND) U5.5(GND) U5.11(PAD) U6.3(GND) U6.4(GND) U6.5(GND) U6.11(PAD) U7.3(GND) U7.4(GND) U7.5(GND) U7.11(PAD)
3V3_VSENSE: C27.2 R82.1 R84.2 U5.6(VSENSE) ; off-sheet 3V3_VSENSE
5V_VSENSE: C38.2 R92.1 R94.2 U6.6(VSENSE) ; off-sheet 5V_VSENSE
12V_VSENSE: C49.2 R102.1 R104.2 U7.6(VSENSE) ; off-sheet 12V_VSENSE
External Power: C22.1 C23.1 C33.1 C34.1 C44.1 C45.1 J4.1(SENSE) J4.2(POWER) J4.3(POWER) J9.1 R81.2 R91.2 R101.2 U5.1(VIN) U6.1(VIN) U7.1(VIN) ; off-sheet External Power
HV_Source: C46.1 C47.1 C48.1 C49.1 J5.1 L4.2 R102.2 ; off-sheet HV_Source
System_3V3: C24.1 C25.1 C26.1 C27.1 J5.3 J7.3 L2.2 R27.2 R82.2 ; off-sheet System_3V3
System_5V: C35.1 C36.1 C37.1 C38.1 J5.2 J7.1 L3.2 R92.2 ; off-sheet System_5V
System_RESET: S3.1 ; off-sheet System_RESET
Tiva_3V3: J7.4 ; off-sheet Tiva_3V3
Tiva_5V: J7.2 ; off-sheet Tiva_5V
NetC20_1: C20.1 U5.9(BOOT)
NetC20_2: C20.2 L2.1 U5.2(PH)
NetC28_1: C28.1 R85.2 U5.7(COMP)
NetC29_1: C29.1 R85.1
NetC30_1: C30.1 R88.2 U5.10(RT)
NetC31_1: C31.1 U6.9(BOOT)
NetC31_2: C31.2 L3.1 U6.2(PH)
NetC39_1: C39.1 R95.2 U6.7(COMP)
NetC40_1: C40.1 R95.1
NetC41_1: C41.1 R97.2 U6.10(RT)
NetC42_1: C42.1 U7.9(BOOT)
NetC42_2: C42.2 L4.1 U7.2(PH)
NetC50_1: C50.1 R108.2 U7.7(COMP)
NetC51_1: C51.1 R108.1
NetC52_1: C52.1 R109.2 U7.10(RT)
NetR27_1: R27.1 S3.2
NetR81_1: R81.1 R83.2 U5.8(EN)
NetR91_1: R91.1 R93.2 U6.8(EN)
NetR101_1: R101.1 R103.2 U7.8(EN)

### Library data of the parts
C20 C23 C26 C31 C34 C37 C42 C45 C48 = C1005X7R1H104M: CAP, CERM, 0.1uF, 50V, +/-20%, C0G/NP0, 0402; Manufacturer: TDK; Polarized: N; CompType: Capacitor; U/M: EA; Cap_F: 0.0000001; Tolerance_%: 20; Value1: Unknown; VDC_V: 50; TaMin_C: -55; TaMax_C: 125
C22 C33 C44 = C2012X5R1E106K125AB: CAP, CERM, 10 µF, 25 V, +/- 10%, X5R, 0805; Manufacturer: TDK; Polarized: N; CompType: Capacitor; Value: 10uF; U/M: EA; Cap_F: 0.00001; Tolerance_%: 10; Value1: Unknown; VDC_V: 25; Value2: 25V; TaMin_C: -55; TaMax_C: 85; Cap_Case: 0805
C24 C25 C35 C36 C46 C47 = C2012X5R1V226M125AC: CAP, CERM, 22 µF, 35 V, +/- 20%, X5R, 0805; Manufacturer: TDK; Polarized: N; CompType: Capacitor; Value: 22uF; U/M: EA; Cap_F: 0.000022; Tolerance_%: 20; Value1: Unknown; VDC_V: 35; Value2: 35V; TaMin_C: -55; TaMax_C: 85; Cap_Case: 0805
C27 C30 C38 C41 C49 C52 = GRM1555C1H121JA01D: CAP, CERM, 120 pF, 50 V, +/- 5%, C0G/NP0, 0402; Manufacturer: MuRata; Polarized: N; CompType: Capacitor; Value: 120pF; U/M: EA; Cap_F: 0.00000000012; Tolerance_%: 5; Value1: Unknown; VDC_V: 50; Value2: 50V; TaMin_C: -55; TaMax_C: 125
C28 = C1005C0G1H331J: CAP, CERM, 330 pF, 50 V, +/- 5%, C0G/NP0, 0402; Manufacturer: TDK; Polarized: N; CompType: Capacitor; Value: 330pF; U/M: EA; Cap_F: 0.00000000033; Tolerance_%: 5; ESR_ohm: 0.0975; Value1: 0.0975 ohm; VDC_V: 50; Value2: 50V; TaMin_C: -55; TaMax_C: 125
C29 = GRM155R71H562KA88D: CAP, CERM, 5600 pF, 50 V, +/- 10%, X7R, 0402; Manufacturer: MuRata; Polarized: N; CompType: Capacitor; Value: 5600pF; U/M: EA; Cap_F: 0.0000000056; Tolerance_%: 10; Value1: Unknown; VDC_V: 50; Value2: 50V; TaMin_C: -55; TaMax_C: 125
C39 = CC0402KRX7R9BB101: CAP, CERM, 100 pF, 50 V, +/- 10%, X7R, 0402; Manufacturer: Yageo America; Polarized: N; CompType: Capacitor; Value: 100pF; U/M: EA; Cap_F: 0.0000000001; Tolerance_%: 10; Value1: Unknown; VDC_V: 50; Value2: 50V; TaMin_C: -55; TaMax_C: 125
C40 = GRM155R61H222KA01D: CAP, CERM, 2200 pF, 50 V, +/- 10%, X5R, 0402; Manufacturer: MuRata; Polarized: N; CompType: Capacitor; Value: 2200pF; U/M: EA; Cap_F: 0.0000000022; Tolerance_%: 10; Value1: Unknown; VDC_V: 50; Value2: 50V; TaMin_C: -55; TaMax_C: 85
C50 = GRM1555C1H910JA01D: CAP, CERM, 91 pF, 50 V, +/- 5%, C0G/NP0, 0402; Manufacturer: MuRata; Polarized: N; CompType: Capacitor; Value: 91pF; U/M: EA; Cap_F: 0.000000000091; Tolerance_%: 5; Value1: Unknown; VDC_V: 50; Value2: 50V; TaMin_C: -55; TaMax_C: 125
C51 = GRM155R71H182KA01D: CAP, CERM, 1800 pF, 50 V, +/- 10%, X7R, 0402; Manufacturer: MuRata; Polarized: N; CompType: Capacitor; Value: 1800pF; U/M: EA; Cap_F: 0.0000000018; Tolerance_%: 10; Value1: Unknown; VDC_V: 50; Value2: 50V; TaMin_C: -55; TaMax_C: 125
J4 = JPD1135-509-7F: Connector,  DC Power Jack, R/A, 3 Pos, TH; Manufacturer: Foxconn; SymbolCreator: a0412235; U/M: EA
J5 = PPPC031LFBN-RC: Receptacle, 100mil, 3x1, Gold, TH; Manufacturer: Sullins Connector Solutions; SymbolCreator: a0412235; U/M: EA
J7 = 15-91-2040: Header, 100mil, 2x2, Tin, SMT; Manufacturer: Molex; SymbolCreator: a0412235; U/M: EA
J9 = 1040: TEST POINT SLOTTED .118", TH; Manufacturer: Keystone; SymbolCreator: a0412235; CompType: Test Point Loop; U/M: EA
L2-L4 = ASPI-0630LR-100M-T15: Manufacturer: ABRACON; SymbolCreator: a0273511; CompType: Inductor; U/M: EA, IN, or GM
R27 = CRCW02011K00FKED: as R12 on sheet HVL117D_Power_Delivery
R81 R91 R101 = CRCW0402220KJNED: RES, 220 k, 5%, 0.063 W, 0402; Manufacturer: Vishay-Dale; CompType: Resistor; Value: 220k; Res_ohm: 220000; Tolerance_%: 5; Power_W: 0.063; Value2: 0.063W; VDC_V: 50; TempCo: 200 ppm/C; EIA_Code: E24; U/M: EA
R82 R92 R102 = CRCW0402100KFKED: RES, 100 k, 1%, 0.063 W, 0402; Manufacturer: Vishay-Dale; CompType: Resistor; Value: 100k; Res_ohm: 100000; Tolerance_%: 1; Power_W: 0.063; Value2: 0.063W; VDC_V: 50; TempCo: 100 ppm/C; EIA_Code: E96; U/M: EA
R83 R93 R103 = CRCW040243K2FKED: RES, 43.2 k, 1%, 0.063 W, 0402; Manufacturer: Vishay-Dale; CompType: Resistor; Value: 43.2k; Res_ohm: 43200; Value_Code: 43k2; Tolerance_%: 1; Power_W: 0.063; Value2: 0.063W; VDC_V: 50; TempCo: 100 ppm/C; EIA_Code: E96; U/M: EA
R84 = CRCW040232K4FKED: RES, 32.4 k, 1%, 0.063 W, 0402; Manufacturer: Vishay-Dale; CompType: Resistor; Value: 32.4k; Res_ohm: 32400; Value_Code: 32k4; Tolerance_%: 1; Power_W: 0.063; Value2: 0.063W; VDC_V: 50; TempCo: 100 ppm/C; EIA_Code: E96; U/M: EA
R85 = CRCW04022K74FKED: RES, 2.74 k, 1%, 0.063 W, 0402; Manufacturer: Vishay-Dale; CompType: Resistor; Value: 2.74k; Res_ohm: 2740; Value_Code: 2k74; Tolerance_%: 1; Power_W: 0.063; Value2: 0.063W; VDC_V: 50; TempCo: 100 ppm/C; EIA_Code: E96; U/M: EA
R88 R97 R109 = CRCW040247K5FKED: RES, 47.5 k, 1%, 0.063 W, 0402; Manufacturer: Vishay-Dale; CompType: Resistor; Value: 47.5k; Res_ohm: 47500; Value_Code: 47k5; Tolerance_%: 1; Power_W: 0.063; Value2: 0.063W; VDC_V: 50; TempCo: 100 ppm/C; EIA_Code: E96; U/M: EA
R94 = CRCW040219K1FKED: RES, 19.1 k, 1%, 0.063 W, 0402; Manufacturer: Vishay-Dale; CompType: Resistor; Value: 19.1k; Res_ohm: 19100; Value_Code: 19k1; Tolerance_%: 1; Power_W: 0.063; Value2: 0.063W; VDC_V: 50; TempCo: 100 ppm/C; EIA_Code: E96; U/M: EA
R95 = CRCW04028K45FKED: RES, 8.45 k, 1%, 0.063 W, 0402; Manufacturer: Vishay-Dale; CompType: Resistor; Value: 8.45k; Res_ohm: 8450; Value_Code: 8k45; Tolerance_%: 1; Power_W: 0.063; Value2: 0.063W; VDC_V: 50; TempCo: 100 ppm/C; EIA_Code: E96; U/M: EA
R104 = CRCW04027K15FKED: RES, 7.15 k, 1%, 0.063 W, 0402; Manufacturer: Vishay-Dale; CompType: Resistor; Value: 7.15k; Res_ohm: 7150; Value_Code: 7k15; Tolerance_%: 1; Power_W: 0.063; Value2: 0.063W; VDC_V: 50; TempCo: 100 ppm/C; EIA_Code: E96; U/M: EA
R108 = CRCW04029K53FKED: RES, 9.53 k, 1%, 0.063 W, 0402; Manufacturer: Vishay-Dale; CompType: Resistor; Value: 9.53k; Res_ohm: 9530; Value_Code: 9k53; Tolerance_%: 1; Power_W: 0.063; Value2: 0.063W; VDC_V: 50; TempCo: 100 ppm/C; EIA_Code: E96; U/M: EA
S3 = B3U-1000P: SWITCH TACTILE SPST-NO 0.05A 12V; Manufacturer: Omron Electronic Components; SymbolCreator: a0412235; VDC_V: 12; SwitchFunction: Off-Mom; PositionCount: 1; CurrentRating_mA: 50
TP5 = 5019: as TP1 on sheet HVL117D_Power_Delivery
U5-U7 = TPS54335DRCR: 4.5V to 28V Input, 3A Output, Synchronous SWIFT Step-Down DC-DC Converter, DRC0010J; Alternate PartNumber: TPS54335DRCT; Manufacturer: Texas Instruments; SymbolCreator: Altium; CompType: IC; U/M: EA

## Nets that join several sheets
GND: HVL117D_Power_Delivery (85 pins), HVL117D_Power_Path (52 pins)
External Power: HVL117D_Power_Delivery (J6.1), HVL117D_Power_Path (16 pins)
HV_Source: HVL117D_Power_Delivery (6 pins), HVL117D_Power_Path (7 pins)
System_3V3: HVL117D_Power_Delivery (C13.1 U2.B1 U2.H1), HVL117D_Power_Path (9 pins)
System_5V: HVL117D_Power_Delivery (15 pins), HVL117D_Power_Path (8 pins)
System_RESET: HVL117D_Power_Delivery (C53.1 R26.2 U2.D6), HVL117D_Power_Path (S3.1)
Tiva_3V3: HVL117D_Power_Delivery (J2.2), HVL117D_Power_Path (J7.4)
Tiva_5V: HVL117D_Power_Delivery (J2.1), HVL117D_Power_Path (J7.2)

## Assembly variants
-001: not fitted C27 C30 C38 C41 C49 C52 FID1 FID2 FID3 FID4 FID5 FID6 H1 H2 H3 H4 H5 H6 H7 H8 J5 J7 R2 R6 R16 R17 R18 R19 R22 R23 R30 R31 R32 R34 R35 R36 R37 R47 R48 R50 R51 R53 R54 R57 R58 R59 R61 R63 R64 R67 R68 R81 R83 R91 R93 R101 R103 S2
UL_TESTING: not fitted C7 C8 C9 C10 C20 C22 C23 C24 C25 C26 C27 C28 C29 C30 C31 C33 C34 C37 C38 C39 C40 C41 C42 C44 C45 C48 C49 C50 C51 C52 D2 D3 D4 D5 D6 D7 D8 D9 FID1 FID2 FID3 FID4 FID5 FID6 H1 H2 H3 H4 H5 H6 H7 H8 J1 J2 J3 J4 J7 L1 L2 L3 L4 Q3 Q4 Q5 Q6 Q7 Q8 Q9 Q10 R2 R6 R16 R17 R18 R19 R20 R22 R23 R24 R27 R30 R31 R32 R34 R35 R36 R37 R38 R40 R46 R47 R48 R50 R51 R53 R54 R57 R58 R59 R60 R61 R62 R63 R64 R65 R66 R67 R68 R69 R70 R71 R72 R73 R74 R75 R76 R77 R78 R79 R80 R81 R82 R83 R84 R85 R86 R87 R88 R90 R91 R92 R93 R94 R95 R96 R97 R101 R102 R103 R104 R108 R109 S3 U3 U4 U5 U6 U7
